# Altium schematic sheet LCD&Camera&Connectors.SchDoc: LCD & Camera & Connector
size A4; DocumentNumber: MB1167; Revision: B.1; SheetNumber: 6; SheetTotal: 17; Project: STM327x6G-EVAL
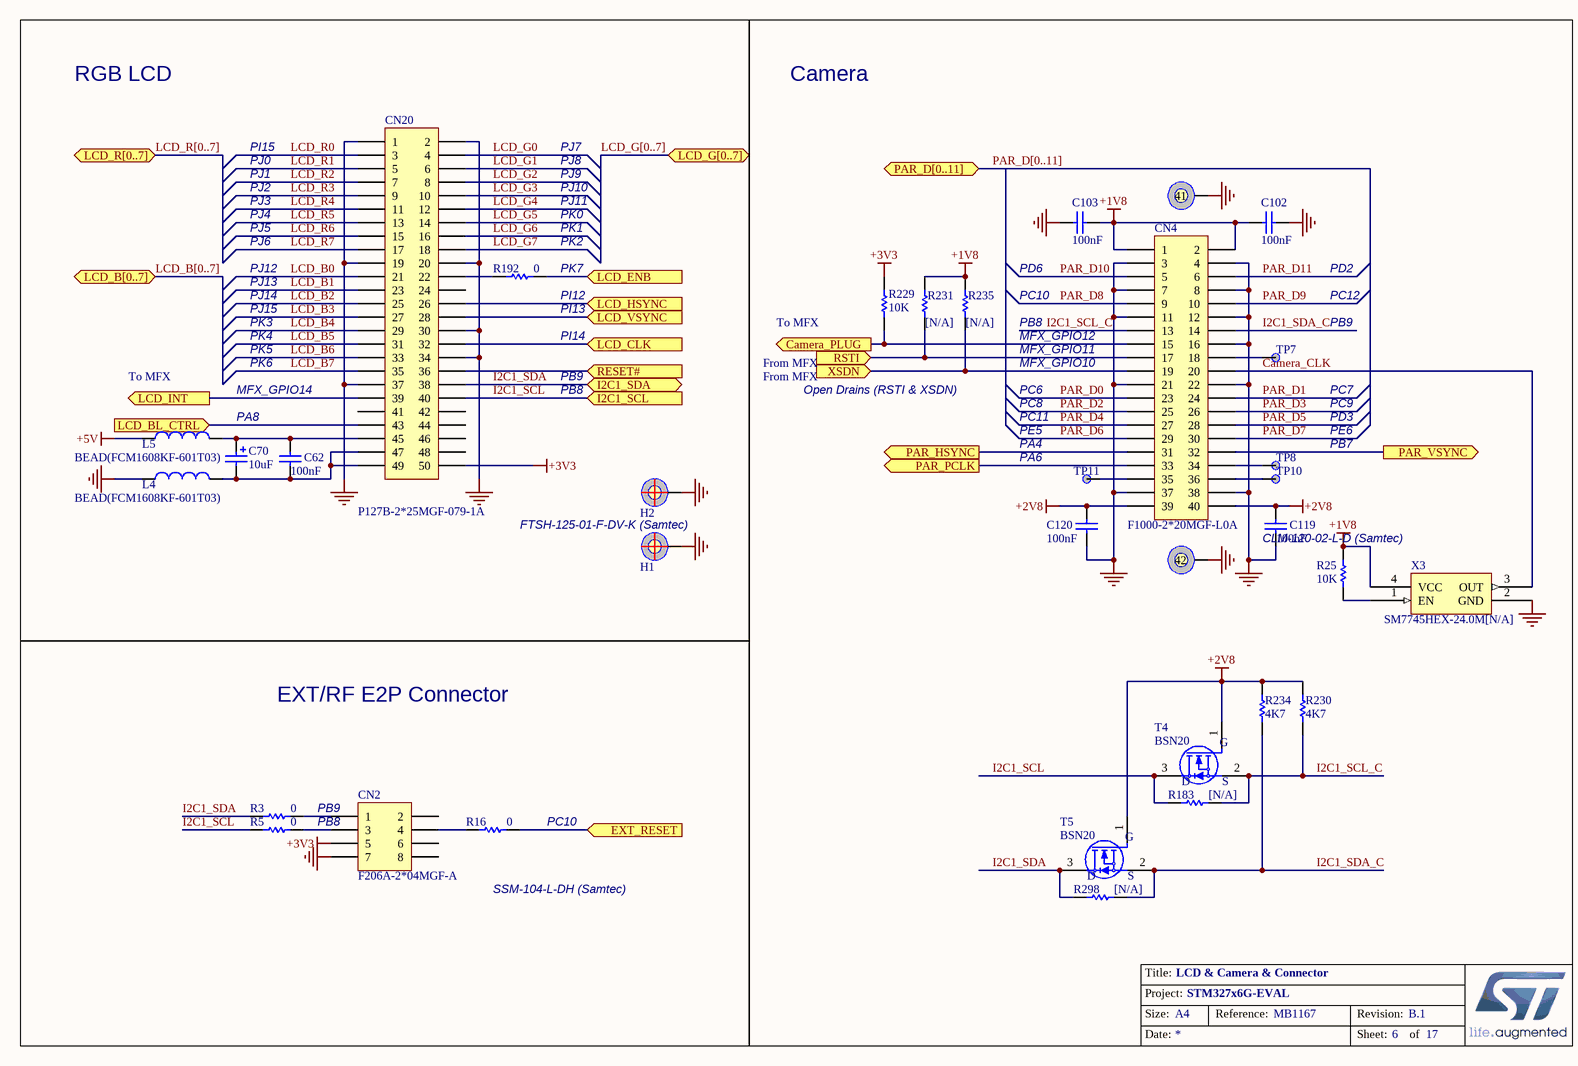
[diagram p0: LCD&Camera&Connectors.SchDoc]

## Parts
C62  100nF  [0603C]
C70  10uF  [TAN-A]
C102  100nF  [0603C]
C103  100nF  [0603C]
C119  100nF  [0603C]
C120  100nF  [0603C]
CN2  F206A-2*04MGF-A  [SSM-104-L-DH]
CN4  F1000-2*20MGF-L0A  [CLM-120-02-L-D]
CN20  P127B-2*25MGF-079-1A  [FTSH-125-01-F-DV]
H1  POSITION HOLE  [HOLE_C9D4R5]  (value not drawn)
H2  POSITION HOLE  [HOLE_C9D4R5]  (value not drawn)
L4  BEAD(FCM1608KF-601T03)  [0603L]
L5  BEAD(FCM1608KF-601T03)  [0603L]
R3  0  [0603R]
R5  0  [0603R]
R16  0  [0603R]
R25  10K  [0402R]
R183  [N/A]  [0603R]
R192  0  [0603R]
R229  10K  [0603R]
R230  4K7  [0603R]
R231  [N/A]  [0603R]
R234  4K7  [0603R]
R235  [N/A]  [0603R]
R298  [N/A]  [0603R]
T4  BSN20  [SOT-23]
T5  BSN20  [SOT-23]
TP7  (no value)  [TP]
TP8  (no value)  [TP]
TP10  (no value)  [TP]
TP11  (no value)  [TP]
X3  SM7745HEX-24.0M[N/A]  [OSC_4SM_7X5]

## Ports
Camera_PLUG (out), EXT_RESET (in), I2C1_SCL (in), I2C1_SDA (bidir), LCD_B[0..7] (bidir), LCD_BL_CTRL (in), LCD_CLK (in), LCD_ENB (in), LCD_G[0..7] (bidir), LCD_HSYNC (in), LCD_INT (out), LCD_R[0..7] (bidir), LCD_VSYNC (in), PAR_D[0..11] (bidir), PAR_HSYNC (out), PAR_PCLK (out), PAR_VSYNC (out), RESET# (in), RSTI (in), XSDN (in)

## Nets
+1V8: C102.1 C103.2 CN4.1 CN4.2 R25.2 R231.2 R235.2 X3.4(VCC)
+2V8: C119.1 C120.1 CN4.39 CN4.40 R230.2 R234.2 T4.1(G) T5.1(G)
+3V3: CN2.5 CN20.50 R229.1
+5V: L5.1
GND: C102.2 C103.1 C119.2 C120.2 CN2.7 CN4.3 CN4.4 CN4.7 CN4.8 CN4.11 CN4.12 CN4.16 CN4.21 CN4.22 CN4.37 CN4.38 CN4.41 CN4.42 CN20.1 CN20.2 CN20.19 CN20.20 CN20.30 CN20.34 CN20.37 H1.1 H2.1 L4.1 X3.2(GND)
Camera_CLK: CN4.20 X3.3(OUT)
Camera_PLUG: CN4.15 R229.2 ; port Camera_PLUG
EXT_RESET: R16.2 ; port EXT_RESET
I2C1_SCL: CN20.40 R5.1 R183.1 T4.3(D) ; port I2C1_SCL
I2C1_SCL_C: CN4.13 R183.2 R230.1 T4.2(S)
I2C1_SDA: CN20.38 R3.1 R298.1 T5.3(D) ; port I2C1_SDA
I2C1_SDA_C: CN4.14 R234.1 R298.2 T5.2(S)
LCD_B0: CN20.21
LCD_B1: CN20.23
LCD_B2: CN20.25
LCD_B3: CN20.27
LCD_B4: CN20.29
LCD_B5: CN20.31
LCD_B6: CN20.33
LCD_B7: CN20.35
LCD_BL_CTRL: CN20.43 ; port LCD_BL_CTRL
LCD_CLK: CN20.32 ; port LCD_CLK
LCD_ENB: R192.2 ; port LCD_ENB
LCD_G0: CN20.4
LCD_G1: CN20.6
LCD_G2: CN20.8
LCD_G3: CN20.10
LCD_G4: CN20.12
LCD_G5: CN20.14
LCD_G6: CN20.16
LCD_G7: CN20.18
LCD_HSYNC: CN20.26 ; port LCD_HSYNC
LCD_INT: CN20.39 ; port LCD_INT
LCD_R0: CN20.3
LCD_R1: CN20.5
LCD_R2: CN20.7
LCD_R3: CN20.9
LCD_R4: CN20.11
LCD_R5: CN20.13
LCD_R6: CN20.15
LCD_R7: CN20.17
LCD_VSYNC: CN20.28 ; port LCD_VSYNC
PAR_D0: CN4.23
PAR_D1: CN4.24
PAR_D2: CN4.25
PAR_D3: CN4.26
PAR_D4: CN4.27
PAR_D5: CN4.28
PAR_D6: CN4.29
PAR_D7: CN4.30
PAR_D8: CN4.9
PAR_D9: CN4.10
PAR_D10: CN4.5
PAR_D11: CN4.6
PAR_HSYNC: CN4.31 ; port PAR_HSYNC
PAR_PCLK: CN4.33 ; port PAR_PCLK
PAR_VSYNC: CN4.32 ; port PAR_VSYNC
RESET#: CN20.36 ; port RESET#
RSTI: CN4.17 R231.1 ; port RSTI
XSDN: CN4.19 R235.1 ; port XSDN
NetC62_1: C62.1 C70.1 CN20.45 L5.2
NetC62_2: C62.2 C70.2 CN20.47 CN20.49 L4.2
NetCN2_1: CN2.1 R3.2
NetCN2_3: CN2.3 R5.2
NetCN2_4: CN2.4 R16.1
NetCN4_18: CN4.18 TP7.1
NetCN4_34: CN4.34 TP8.1
NetCN4_35: CN4.35 TP11.1
NetCN4_36: CN4.36 TP10.1
NetCN20_22: CN20.22 R192.1
NetR25_1: R25.1 X3.1(EN)

Not connected (* = marked no-connect by the designer): CN2 2 6 8; CN20 24 41 42 44 46 48

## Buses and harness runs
bus LCD_B[0..7] = port LCD_B[0..7]
bus LCD_G[0..7] = port LCD_G[0..7]
bus LCD_R[0..7] = port LCD_R[0..7]
bus PAR_D[0..11] = port PAR_D[0..11]

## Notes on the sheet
- RGB LCD
- Camera
- PI15
- PJ0
- PJ1
- PJ2
- PJ7
- PJ8
- PJ9
- PJ10
- PJ3
- PJ4
- PJ5
- PJ6
- PJ11
- PK0
- (near R192) PK1
- (near R192) PK2
- PJ12
- PJ13
- PJ14
- PJ15
- PK3
- (near R192) PK7
- (near R192) PI12
- (near R192) PI13
- To MFX
- PC10
- PB8
- PD6
- PB9
- PD2
- PC12
- MFX_GPIO14
- PK4
- PK5
- PK6
- PI14
- From MFX
- Open Drains (RSTI & XSDN)
- PC6
- MFX_GPIO12
- MFX_GPIO10
- MFX_GPIO11
- PC7
- PA8
- PC11
- PE5
- PA4
- PA6
- PC8
- PE6
- PC9
- PB7
- PD3
- FTSH-125-01-F-DV-K (Samtec)
- (near CN4) CLM-120-02-L-D (Samtec)
- EXT/RF E2P Connector
- (near R16) PC10
- (near CN2) SSM-104-L-DH (Samtec)

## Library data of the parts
C62 C102 C103 C119 C120 = Cap: Capacitor; Value: 10nF
C70 = Cap Pol1: Polarized Capacitor (Radial)
CN2 = SSM-104-L-DH: Header, 5-Pin, Dual row
CN4 = CLM-120-02-L-D: Header, 20-Pin, Dual row
CN20 = Header 25X2: Header, 26-Pin, Dual row
L4 L5 = Inductor: Value: 100uH
R3 R5 R16 R25 R183 R192 R229 R298 = Res1: Resistor; Value: 1K
R230 R231 R234 R235 = res1: Resistor; Value: 1K
T4 T5 = 2N7000
TP7 TP8 TP10 TP11 = TP
X3 = SM7745HEV-50.0M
